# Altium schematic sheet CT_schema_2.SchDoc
size 276 x 169 mm
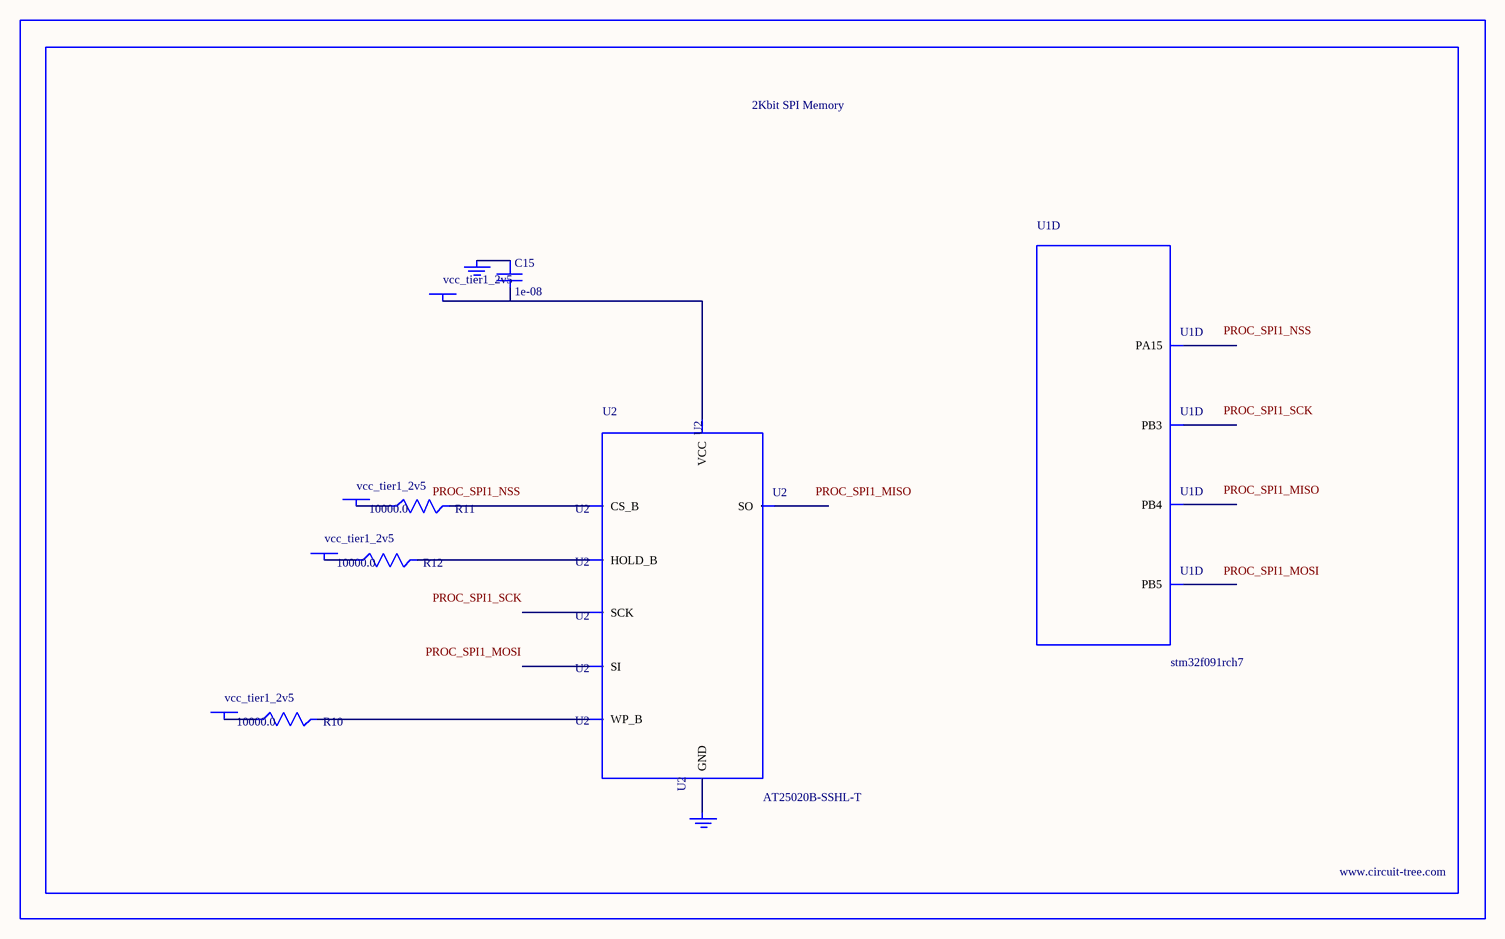
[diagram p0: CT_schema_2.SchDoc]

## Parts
BORDER1  (no value)
C15  1e-08  [C0402]
GND_INSTANCE_1_0  (no value)
GND_INSTANCE_1_1  (no value)
POWER_INSTANCE_1_0  vcc_tier1_2v5
POWER_INSTANCE_1_1  vcc_tier1_2v5
POWER_INSTANCE_1_2  vcc_tier1_2v5
POWER_INSTANCE_1_3  vcc_tier1_2v5
R10  10000.0  [R0603]
R11  10000.0  [R0603]
R12  10000.0  [R0603]
U1  stm32f091rch7  [UFBGA64]  (part D of 6)
U2  AT25020B-SSHL-T  [SOIC-8]

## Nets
NetC15_1: C15.1 GND_INSTANCE_1_0.0(GND)
NetC15_2: C15.2 POWER_INSTANCE_1_3.0(PWR) U2.8(VCC)
NetGND_INSTANCE_1_1_0: GND_INSTANCE_1_1.0(GND) U2.4(GND)
NetPOWER_INSTANCE_1_0_0: POWER_INSTANCE_1_0.0(PWR) R11.1
NetPOWER_INSTANCE_1_1_0: POWER_INSTANCE_1_1.0(PWR) R10.1
NetPOWER_INSTANCE_1_2_0: POWER_INSTANCE_1_2.0(PWR) R12.1
NetR10_2: R10.2 U2.3(WP_B)
NetR11_2: R11.2 U2.1(CS_B)
NetR12_2: R12.2 U2.7(HOLD_B)

Not connected (* = marked no-connect by the designer): U1 A4(PB4) A5(PB3) A6(PA15) C4(PB5); U2 2(SO) 5(SI) 6(SCK)

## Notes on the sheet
- Labels drawn without touching a wire or pin: PROC_SPI1_MISO, PROC_SPI1_MOSI, PROC_SPI1_NSS, PROC_SPI1_SCK

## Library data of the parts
BORDER1 = BORDER_PAGE1
C15 = C0402C103K3RAC
GND_INSTANCE_1_0 GND_INSTANCE_1_1 = GND
POWER_INSTANCE_1_0-POWER_INSTANCE_1_3 = PWR
R10-R12 = RC0603JR-0710KL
